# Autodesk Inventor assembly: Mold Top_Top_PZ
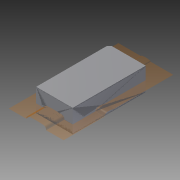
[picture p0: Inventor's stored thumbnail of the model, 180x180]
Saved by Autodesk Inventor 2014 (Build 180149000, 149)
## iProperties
Created: 2009-12
Part Number: Mold Top_Top_PZ
Document SubType Name: Assembly
Designer: gaom
Author: gaom
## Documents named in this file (10)
- C:\Users\iTools\Desktop\tutorial files\Mold\Mold Structural Assembly\Mold Top\Mold Top_Top_PZ.iam
- C:\Users\iTools\Desktop\tutorial files\Mold\Mold Structural Assembly\Mold Top\Mold Top_Top_MP.ipt
- C:\Users\iTools\Desktop\tutorial files\Mold\Mold Structural Assembly\Mold Top\Mold Top_Top_WP.ipt
- C:\Users\iTools\Desktop\tutorial files\Mold\Mold Structural Assembly\Mold Top\Mold Top_Top_CR_Base.ipt
- C:\Users\iTools\Desktop\tutorial files\Mold\Mold Structural Assembly\Mold Top\Mold Top_Top_CR_1.ipt
- C:\Users\iTools\Desktop\tutorial files\Mold\Mold Structural Assembly\Mold Top\Mold Top_Top_CV_Base.ipt
- C:\Users\iTools\Desktop\tutorial files\Mold\Mold Structural Assembly\Mold Top\Mold Top_Top_CV_1.ipt
- C:\Users\iTools\Desktop\tutorial files\Mold\Mold Structural Assembly\Mold Top\Mold Top_Top_IS.ipt
- C:\Users\iTools\Desktop\tutorial files\Mold\Mold Structural Assembly\Mold Top\Mold Top_Top_IN3_Base.ipt
- C:\Users\iTools\Desktop\tutorial files\Mold\Mold Structural Assembly\Mold Top\Mold Top_Top_IN3_1_1.ipt
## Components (9 placed, 9 different names)
1. Mold Top_Top_MP:1 — Flush:1, Flush:2, Flush:3, Flush:4, Flush:5, Flush:6
2. Mold Top_Top_WP:1 — Flush:4, Flush:5, Flush:6
3. Mold Top_Top_CR_Base:1 — Flush:7, Flush:8, Flush:9, Flush:13, Flush:14, Flush:15
4. Mold Top_Top_CR_1:1 — Flush:13, Flush:14, Flush:15
5. Mold Top_Top_CV_Base:1 — Flush:10, Flush:11, Flush:12, Flush:16, Flush:17, Flush:18
6. Mold Top_Top_CV_1:1 — Flush:16, Flush:17, Flush:18, Flush:25, Flush:26, Flush:27
7. Mold Top_Top_IS:1
8. Mold Top_Top_IN3_Base:1 — Flush:19, Flush:20, Flush:21, Flush:22, Flush:23, Flush:24
9. Mold Top_Top_IN3_1_1:1 — Flush:22, Flush:23, Flush:24, Flush:25, Flush:26, Flush:27
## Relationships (27: Flush 27)
- Flush:1: Mold Top_Top_MP:1
- Flush:2: Mold Top_Top_MP:1
- Flush:3: Mold Top_Top_MP:1
- Flush:4: Mold Top_Top_MP:1 ↔ Mold Top_Top_WP:1
- Flush:5: Mold Top_Top_MP:1 ↔ Mold Top_Top_WP:1
- Flush:6: Mold Top_Top_MP:1 ↔ Mold Top_Top_WP:1
- Flush:7: Mold Top_Top_CR_Base:1
- Flush:8: Mold Top_Top_CR_Base:1
- Flush:9: Mold Top_Top_CR_Base:1
- Flush:10: Mold Top_Top_CV_Base:1
- Flush:11: Mold Top_Top_CV_Base:1
- Flush:12: Mold Top_Top_CV_Base:1
- Flush:13: Mold Top_Top_CR_Base:1 ↔ Mold Top_Top_CR_1:1
- Flush:14: Mold Top_Top_CR_Base:1 ↔ Mold Top_Top_CR_1:1
- Flush:15: Mold Top_Top_CR_Base:1 ↔ Mold Top_Top_CR_1:1
- Flush:16: Mold Top_Top_CV_Base:1 ↔ Mold Top_Top_CV_1:1
- Flush:17: Mold Top_Top_CV_Base:1 ↔ Mold Top_Top_CV_1:1
- Flush:18: Mold Top_Top_CV_Base:1 ↔ Mold Top_Top_CV_1:1
- Flush:19: Mold Top_Top_IN3_Base:1
- Flush:20: Mold Top_Top_IN3_Base:1
- Flush:21: Mold Top_Top_IN3_Base:1
- Flush:22: Mold Top_Top_IN3_Base:1 ↔ Mold Top_Top_IN3_1_1:1
- Flush:23: Mold Top_Top_IN3_Base:1 ↔ Mold Top_Top_IN3_1_1:1
- Flush:24: Mold Top_Top_IN3_Base:1 ↔ Mold Top_Top_IN3_1_1:1
- Flush:25: Mold Top_Top_CV_1:1 ↔ Mold Top_Top_IN3_1_1:1
- Flush:26: Mold Top_Top_CV_1:1 ↔ Mold Top_Top_IN3_1_1:1
- Flush:27: Mold Top_Top_CV_1:1 ↔ Mold Top_Top_IN3_1_1:1
